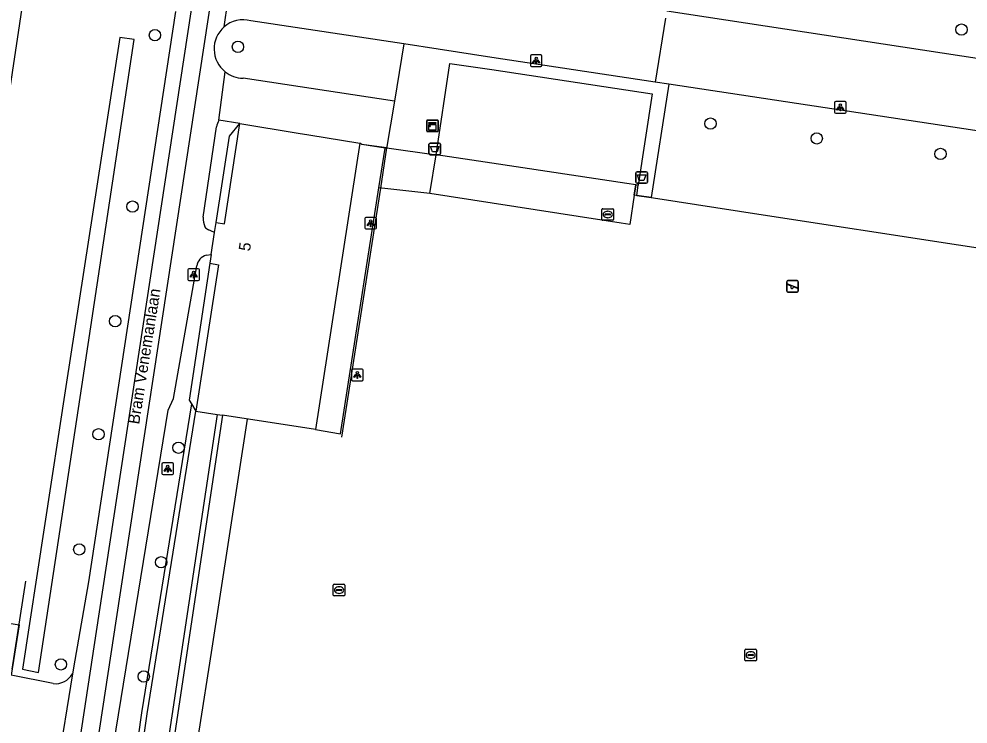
# Model space of a CAD drawing. Extents: x 161094 to 161705, y 379509 to 380907.
# Drawn here: x 161459.2 to 161541.1, y 380220.9 to 380281.7 of the extents above; entities that cross this region are included whole.
import ezdxf

# ---------------------------------------------------------------- set-up
doc = ezdxf.new("R2010")
doc.units = 0
for name, color, linetype in [('IMGEO_Afvalbak', 7, 'Continuous'), ('IMGEO_Boom', 7, 'Continuous'), ('IMGEO_Greppel_droge_sloot', 7, 'Continuous'), ('IMGEO_Groenvoorziening', 7, 'Continuous'), ('IMGEO_Hek', 7, 'Continuous'), ('IMGEO_Kast', 7, 'Continuous'), ('IMGEO_Lichtpunt', 7, 'Continuous'), ('IMGEO_Openbare_ruimte_label', 7, 'Continuous'), ('IMGEO_Pand', 7, 'Continuous'), ('IMGEO_Pand_nummerreeks', 7, 'Continuous'), ('IMGEO_Rijbaan_lokaal_gesloten', 7, 'Continuous'), ('IMGEO_Rijbaan_lokaal_open', 7, 'Continuous'), ('IMGEO_Speelvoorziening', 7, 'Continuous'), ('IMGEO_Voetpad_gesloten', 7, 'Continuous'), ('IMGEO_Voetpad_halfverhard', 7, 'Continuous'), ('IMGEO_Voetpad_open', 7, 'Continuous'), ('IMGEO_Waterleidingput', 7, 'Continuous'), ('IMGEO_Waterloop', 7, 'Continuous')]:
    doc.layers.add(name, color=color, linetype=linetype)

msp = doc.modelspace()

# ---------------------------------------------------------------- linework, layer by layer
at = {"layer": 'IMGEO_Afvalbak'}
for p, q in [((161494.577, 380270.094), (161494.577, 380270.894)), ((161494.577, 380270.894), (161494.577, 380270.094)), ((161494.677, 380270.994), (161495.467, 380270.994)), ((161495.467, 380270.994), (161494.677, 380270.994)), ((161495.567, 380270.894), (161495.567, 380270.094)), ((161495.567, 380270.094), (161495.567, 380270.894)), ((161495.467, 380269.994), (161494.677, 380269.994)), ((161494.677, 380269.994), (161495.467, 380269.994)), ((161512.428, 380267.629), (161512.428, 380268.429)), ((161512.428, 380268.429), (161512.428, 380267.629)), ((161512.528, 380268.529), (161513.318, 380268.529)), ((161513.318, 380268.529), (161512.528, 380268.529)), ((161513.418, 380268.429), (161513.418, 380267.629)), ((161513.418, 380267.629), (161513.418, 380268.429)), ((161513.318, 380267.529), (161512.528, 380267.529)), ((161512.528, 380267.529), (161513.318, 380267.529))]:
    msp.add_line(p, q, dxfattribs=at)
for points in [[(161494.72, 380270.708), (161495.424, 380270.708), (161495.275, 380270.238), (161494.869, 380270.238), (161494.72, 380270.708)], [(161512.571, 380268.243), (161513.275, 380268.243), (161513.126, 380267.773), (161512.72, 380267.773), (161512.571, 380268.243)]]:
    msp.add_lwpolyline(points, dxfattribs=at)
for centre, start, end in [((161494.677, 380270.894), 90, 180), ((161494.677, 380270.894), 90, 180), ((161495.467, 380270.894), 0, 90), ((161495.467, 380270.894), 360, 90), ((161494.677, 380270.094), 180, 270), ((161494.677, 380270.094), 180, 270), ((161495.467, 380270.094), 270, 0), ((161495.467, 380270.094), 270, 0), ((161512.528, 380268.429), 90, 180), ((161512.528, 380268.429), 90, 180), ((161513.318, 380268.429), 0, 90), ((161513.318, 380268.429), 360, 90), ((161512.528, 380267.629), 180, 270), ((161512.528, 380267.629), 180, 270), ((161513.318, 380267.629), 270, 0), ((161513.318, 380267.629), 270, 0)]:
    msp.add_arc(centre, 0.1, start, end, dxfattribs=at)
at = {"layer": 'IMGEO_Boom'}
for centre in [(161540.519, 380280.781), (161470.934, 380280.302), (161478.097, 380279.294), (161518.864, 380272.671), (161528.028, 380271.401), (161538.709, 380270.057), (161468.994, 380265.516), (161467.497, 380255.64), (161466.065, 380245.889), (161472.961, 380244.732), (161464.403, 380235.963), (161471.464, 380234.855), (161462.817, 380226.049), (161469.968, 380225.004)]:
    msp.add_circle(centre, 0.489, dxfattribs=at)
at = {"layer": 'IMGEO_Greppel_droge_sloot'}
msp.add_lwpolyline([(161469.146, 380279.911), (161467.896, 380280.089), (161463.253, 380250), (161459.495, 380225.647), (161460.876, 380225.356), (161464.612, 380250), (161469.146, 380279.911)], dxfattribs=at)
at = {"layer": 'IMGEO_Groenvoorziening'}
for points in [[(161476.2, 380264.154), (161477.368, 380271.592), (161478.255, 380272.694)], [(161512.415, 380267.391), (161512.279, 380266.508), (161511.902, 380263.976), (161511.145, 380264.094), (161494.657, 380266.645)], [(161475.658, 380260.635), (161473.892, 380248.836), (161474.092, 380248.508)], [(161474.092, 380248.508), (161469.784, 380221.87), (161463.517, 380177.6), (161462.422, 380170.033), (161462.392, 380169.879), (161462.385, 380169.673), (161462.409, 380169.469), (161462.437, 380169.367)], [(161474.092, 380248.508), (161474.472, 380247.886)], [(161476.761, 380247.535), (161466.509, 380179.329), (161465.043, 380169.711), (161465.035, 380169.551), (161465.006, 380169.36)]]:
    msp.add_lwpolyline(points, dxfattribs=at)
at = {"layer": 'IMGEO_Hek'}
for points in [[(161487.042, 380245.645), (161490.407, 380267.114), (161490.951, 380270.588)], [(161490.951, 380270.588), (161488.77, 380270.861)], [(161490.951, 380270.588), (161495.182, 380269.995)], [(161512.279, 380266.508), (161512.415, 380267.391)], [(161574.717, 380256.895), (161523.039, 380264.851), (161512.279, 380266.508)], [(161512.509, 380266.485), (161513.755, 380266.304)], [(161558.655, 380153.718), (161472.202, 380166.92), (161467.427, 380173.551), (161469.43, 380186.379), (161475.815, 380227.062), (161478.929, 380247.203)], [(161458.621, 380225.641), (161459.791, 380233.223)]]:
    msp.add_lwpolyline(points, dxfattribs=at)
at = {"layer": 'IMGEO_Kast'}
for p, q in [((161494.376, 380272.058), (161494.376, 380272.899)), ((161494.376, 380272.899), (161494.376, 380272.058)), ((161494.451, 380272.983), (161495.292, 380272.983)), ((161495.292, 380272.983), (161494.451, 380272.983)), ((161495.376, 380272.908), (161495.376, 380272.067)), ((161495.376, 380272.067), (161495.376, 380272.908)), ((161495.301, 380271.983), (161494.46, 380271.983)), ((161494.46, 380271.983), (161495.301, 380271.983))]:
    msp.add_line(p, q, dxfattribs=at)
for points in [[(161494.571, 380272.773), (161495.171, 380272.773), (161495.171, 380272.688), (161494.571, 380272.688), (161494.571, 380272.773)], [(161494.571, 380272.598), (161495.171, 380272.598), (161495.171, 380272.109), (161494.571, 380272.109), (161494.571, 380272.598)]]:
    msp.add_lwpolyline(points, dxfattribs=at)
msp.add_circle((161494.655, 380272.447), 0.0377, dxfattribs=at)
for centre, start, end in [((161494.454, 380272.905), 92.4484, 184.28452), ((161494.454, 380272.905), 92.4484, 184.28452), ((161495.298, 380272.905), 2.4484, 94.28452), ((161495.298, 380272.905), 2.4484, 94.28452), ((161494.454, 380272.061), 182.4484, 274.28452), ((161494.454, 380272.061), 182.4484, 274.28452), ((161495.298, 380272.061), 272.4484, 4.28452), ((161495.298, 380272.061), 272.4484, 4.28452)]:
    msp.add_arc(centre, 0.0779, start, end, dxfattribs=at)
at = {"layer": 'IMGEO_Lichtpunt'}
for p, q in [((161503.326, 380278.5), (161503.326, 380277.693)), ((161503.326, 380278.5), (161503.326, 380277.693)), ((161504.228, 380278.595), (161503.42, 380278.595)), ((161504.228, 380278.595), (161503.42, 380278.595)), ((161504.322, 380277.693), (161504.322, 380278.5)), ((161504.322, 380277.693), (161504.322, 380278.5)), ((161503.42, 380277.599), (161504.228, 380277.599)), ((161503.42, 380277.599), (161504.228, 380277.599)), ((161529.572, 380274.471), (161529.572, 380273.664)), ((161529.572, 380274.471), (161529.572, 380273.664)), ((161530.474, 380274.566), (161529.666, 380274.566)), ((161530.474, 380274.566), (161529.666, 380274.566)), ((161530.568, 380273.664), (161530.568, 380274.471)), ((161530.568, 380273.664), (161530.568, 380274.471)), ((161529.666, 380273.57), (161530.474, 380273.57)), ((161529.666, 380273.57), (161530.474, 380273.57)), ((161489.945, 380264.585), (161489.137, 380264.585)), ((161489.945, 380264.585), (161489.137, 380264.585)), ((161489.043, 380264.49), (161489.043, 380263.683)), ((161489.043, 380264.49), (161489.043, 380263.683)), ((161490.039, 380263.683), (161490.039, 380264.49)), ((161490.039, 380263.683), (161490.039, 380264.49)), ((161489.137, 380263.589), (161489.945, 380263.589)), ((161489.137, 380263.589), (161489.945, 380263.589)), ((161473.771, 380260.054), (161473.771, 380259.247)), ((161473.771, 380260.054), (161473.771, 380259.247)), ((161474.673, 380260.149), (161473.865, 380260.149)), ((161474.673, 380260.149), (161473.865, 380260.149)), ((161474.767, 380259.247), (161474.767, 380260.054)), ((161474.767, 380259.247), (161474.767, 380260.054)), ((161473.865, 380259.153), (161474.673, 380259.153)), ((161473.865, 380259.153), (161474.673, 380259.153)), ((161488.798, 380251.499), (161487.99, 380251.499)), ((161488.798, 380251.499), (161487.99, 380251.499)), ((161487.896, 380251.404), (161487.896, 380250.597)), ((161487.896, 380251.404), (161487.896, 380250.597)), ((161488.892, 380250.597), (161488.892, 380251.404)), ((161488.892, 380250.597), (161488.892, 380251.404)), ((161487.99, 380250.503), (161488.798, 380250.503)), ((161487.99, 380250.503), (161488.798, 380250.503)), ((161471.539, 380243.318), (161471.539, 380242.511)), ((161471.539, 380243.318), (161471.539, 380242.511)), ((161472.441, 380243.413), (161471.633, 380243.413)), ((161472.441, 380243.413), (161471.633, 380243.413)), ((161472.535, 380242.511), (161472.535, 380243.318)), ((161472.535, 380242.511), (161472.535, 380243.318)), ((161471.633, 380242.417), (161472.441, 380242.417)), ((161471.633, 380242.417), (161472.441, 380242.417))]:
    msp.add_line(p, q, dxfattribs=at)
for points in [[(161503.7, 380278.164), (161503.739, 380278.136), (161503.551, 380277.874), (161503.513, 380277.901), (161503.7, 380278.164)], [(161503.802, 380278.116), (161503.849, 380278.116), (161503.849, 380277.794), (161503.802, 380277.794), (161503.802, 380278.116)], [(161503.912, 380278.136), (161503.95, 380278.163), (161504.137, 380277.901), (161504.098, 380277.873), (161503.912, 380278.136)], [(161529.946, 380274.135), (161529.985, 380274.107), (161529.797, 380273.845), (161529.759, 380273.872), (161529.946, 380274.135)], [(161530.048, 380274.087), (161530.095, 380274.087), (161530.095, 380273.765), (161530.048, 380273.765), (161530.048, 380274.087)], [(161530.158, 380274.107), (161530.196, 380274.134), (161530.383, 380273.872), (161530.344, 380273.844), (161530.158, 380274.107)], [(161489.417, 380264.154), (161489.456, 380264.126), (161489.268, 380263.864), (161489.23, 380263.891), (161489.417, 380264.154)], [(161489.519, 380264.106), (161489.566, 380264.106), (161489.566, 380263.784), (161489.519, 380263.784), (161489.519, 380264.106)], [(161489.629, 380264.126), (161489.667, 380264.153), (161489.854, 380263.891), (161489.815, 380263.863), (161489.629, 380264.126)], [(161474.145, 380259.718), (161474.184, 380259.69), (161473.996, 380259.428), (161473.958, 380259.455), (161474.145, 380259.718)], [(161474.247, 380259.67), (161474.294, 380259.67), (161474.294, 380259.348), (161474.247, 380259.348), (161474.247, 380259.67)], [(161474.357, 380259.69), (161474.395, 380259.717), (161474.582, 380259.455), (161474.543, 380259.427), (161474.357, 380259.69)], [(161488.27, 380251.068), (161488.309, 380251.04), (161488.121, 380250.778), (161488.083, 380250.805), (161488.27, 380251.068)], [(161488.372, 380251.02), (161488.419, 380251.02), (161488.419, 380250.698), (161488.372, 380250.698), (161488.372, 380251.02)], [(161488.482, 380251.04), (161488.52, 380251.067), (161488.707, 380250.805), (161488.668, 380250.777), (161488.482, 380251.04)], [(161471.913, 380242.982), (161471.952, 380242.954), (161471.764, 380242.692), (161471.726, 380242.719), (161471.913, 380242.982)], [(161472.015, 380242.934), (161472.062, 380242.934), (161472.062, 380242.612), (161472.015, 380242.612), (161472.015, 380242.934)], [(161472.125, 380242.954), (161472.163, 380242.981), (161472.35, 380242.719), (161472.311, 380242.691), (161472.125, 380242.954)]]:
    msp.add_lwpolyline(points, dxfattribs=at)
for centre in [(161503.825, 380278.298), (161530.071, 380274.269), (161489.542, 380264.288), (161474.27, 380259.852), (161488.395, 380251.202), (161472.038, 380243.116)]:
    msp.add_circle(centre, 0.0994, dxfattribs=at)
for centre, start, end in [((161503.42, 380278.5), 90, 180), ((161503.42, 380278.5), 90, 180), ((161504.228, 380278.5), 0, 90), ((161504.228, 380278.5), 0, 90), ((161503.42, 380277.693), 180, 270), ((161503.42, 380277.693), 180, 270), ((161504.228, 380277.693), 270, 0), ((161504.228, 380277.693), 270, 360), ((161529.666, 380274.471), 90, 180), ((161529.666, 380274.471), 90, 180), ((161530.474, 380274.471), 0, 90), ((161530.474, 380274.471), 0, 90), ((161529.666, 380273.664), 180, 270), ((161529.666, 380273.664), 180, 270), ((161530.474, 380273.664), 270, 0), ((161530.474, 380273.664), 270, 360), ((161489.137, 380264.49), 90, 180), ((161489.137, 380264.49), 90, 180), ((161489.945, 380264.49), 0, 90), ((161489.945, 380264.49), 0, 90), ((161489.137, 380263.683), 180, 270), ((161489.137, 380263.683), 180, 270), ((161489.945, 380263.683), 270, 0), ((161489.945, 380263.683), 270, 360), ((161473.865, 380260.054), 90, 180), ((161473.865, 380260.054), 90, 180), ((161474.673, 380260.054), 0, 90), ((161474.673, 380260.054), 0, 90), ((161473.865, 380259.247), 180, 270), ((161473.865, 380259.247), 180, 270), ((161474.673, 380259.247), 270, 0), ((161474.673, 380259.247), 270, 360), ((161487.99, 380251.404), 90, 180), ((161487.99, 380251.404), 90, 180), ((161488.798, 380251.404), 0, 90), ((161488.798, 380251.404), 0, 90), ((161487.99, 380250.597), 180, 270), ((161487.99, 380250.597), 180, 270), ((161488.798, 380250.597), 270, 0), ((161488.798, 380250.597), 270, 360), ((161471.633, 380243.318), 90, 180), ((161471.633, 380243.318), 90, 180), ((161472.441, 380243.318), 0, 90), ((161472.441, 380243.318), 0, 90), ((161471.633, 380242.511), 180, 270), ((161471.633, 380242.511), 180, 270), ((161472.441, 380242.511), 270, 0), ((161472.441, 380242.511), 270, 360)]:
    msp.add_arc(centre, 0.0946, start, end, dxfattribs=at)
at = {"layer": 'IMGEO_Pand'}
for points in [[(161445.404, 380233.707), (161445.627, 380235.147), (161446.05, 380235.084), (161452.191, 380234.169), (161452.226, 380234.4), (161454.566, 380250), (161468.027, 380339.705), (161467.674, 380339.759)], [(161495.182, 380269.995), (161496.387, 380277.87), (161500, 380277.328), (161513.842, 380275.25), (161512.618, 380267.36)], [(161476.2, 380264.154), (161476.94, 380264.03), (161478.255, 380272.694)], [(161478.255, 380272.694), (161483.281, 380271.863), (161484.207, 380271.71), (161488.622, 380270.98)], [(161488.622, 380270.98), (161484.775, 380246.307)], [(161512.415, 380267.391), (161511.66, 380267.505), (161500, 380269.267), (161495.182, 380269.995)], [(161512.618, 380267.36), (161512.415, 380267.391)], [(161476.066, 380263.282), (161476.2, 380264.154)], [(161475.772, 380261.375), (161476.066, 380263.282)], [(161475.772, 380261.375), (161475.658, 380260.635)], [(161475.658, 380260.635), (161476.425, 380260.498), (161474.472, 380247.886)], [(161474.472, 380247.886), (161476.294, 380247.607)], [(161476.294, 380247.607), (161476.761, 380247.535)], [(161484.775, 380246.307), (161476.761, 380247.535)]]:
    msp.add_lwpolyline(points, dxfattribs=at)
at = {"layer": 'IMGEO_Rijbaan_lokaal_gesloten'}
for points in [[(161500.797, 380441.248), (161498.535, 380426.719), (161497.303, 380424.898), (161496.967, 380422.687), (161487.325, 380359.344), (161487.307, 380359.083), (161485.505, 380347.041), (161467.599, 380229.99), (161457.567, 380164.364), (161456.074, 380164.596), (161466.094, 380230.202), (161483.979, 380347.225), (161485.809, 380359.378), (161485.861, 380359.57), (161495.524, 380423.042), (161498.373, 380441.757)], [(161476.894, 380281.005), (161478.163, 380289.777)], [(161472.691, 380282.325), (161465.207, 380233.179), (161464.029, 380226.403), (161463.827, 380225.238)], [(161492.398, 380279.538), (161479.202, 380281.544)], [(161514.984, 380281.757), (161514.092, 380276.241)], [(161514.092, 380276.241), (161500, 380278.383), (161495.36, 380279.088), (161492.398, 380279.538)], [(161476.447, 380272.956), (161476.982, 380277.141)], [(161475.082, 380264.596), (161476.248, 380272.398)], [(161476.066, 380263.282), (161476.007, 380263.315), (161475.555, 380263.529)], [(161475.343, 380261.323), (161475.772, 380261.375)], [(161459.926, 380169.997), (161464.514, 380200.592), (161467.572, 380220.455), (161472.065, 380247.978), (161472.522, 380248.965), (161474.536, 380260.41)], [(161463.827, 380225.238), (161462.538, 380217.249), (161462.38, 380216.189)]]:
    msp.add_lwpolyline(points, dxfattribs=at)
for centre, radius, start, end in [((161478.554, 380279.11), 2.519, 131.2084, 231.40089), ((161478.553, 380279.11), 2.519, 75.08028, 131.20974), ((161478.34, 380271.966), 2.136, 152.40098, 168.34342), ((161477.584, 380264.669), 2.503, 181.6754, 201.05116), ((161475.707, 380264.038), 0.531, 210.32108, 253.41394), ((161475.716, 380260.18), 1.202, 108.0641, 168.98902)]:
    msp.add_arc(centre, radius, start, end, dxfattribs=at)
at = {"layer": 'IMGEO_Rijbaan_lokaal_open'}
for points in [[(161574.117, 380277.813), (161571.082, 380273.823), (161515.085, 380282.382)], [(161574.117, 380277.813), (161578.015, 380277.213), (161578.015, 380271.799), (161576.918, 380266.95), (161571.501, 380267.574), (161515.278, 380276.061)], [(161515.278, 380276.061), (161514.092, 380276.241)]]:
    msp.add_lwpolyline(points, dxfattribs=at)
at = {"layer": 'IMGEO_Speelvoorziening'}
for p, q in [((161525.449, 380258.238), (161525.449, 380259.038)), ((161525.449, 380259.038), (161525.449, 380258.238)), ((161525.518, 380258.863), (161526.394, 380258.51)), ((161525.549, 380259.138), (161526.339, 380259.138)), ((161526.339, 380259.138), (161525.549, 380259.138)), ((161526.439, 380259.038), (161526.439, 380258.238)), ((161526.439, 380258.238), (161526.439, 380259.038)), ((161525.832, 380258.666), (161525.493, 380258.803)), ((161526.339, 380258.138), (161525.549, 380258.138)), ((161525.549, 380258.138), (161526.339, 380258.138)), ((161526.37, 380258.45), (161526.03, 380258.587))]:
    msp.add_line(p, q, dxfattribs=at)
for centre, radius, start, end in [((161525.549, 380259.038), 0.1, 90, 180), ((161525.549, 380259.038), 0.1, 90, 180), ((161525.506, 380258.833), 0.0327, 68.07798, 248.07798), ((161526.339, 380259.038), 0.1, 0, 90), ((161526.339, 380259.038), 0.1, 360, 90), ((161525.549, 380258.238), 0.1, 180, 270), ((161525.549, 380258.238), 0.1, 180, 270), ((161525.911, 380258.576), 0.12, 130.99278, 5.16318), ((161526.339, 380258.238), 0.1, 270, 0), ((161526.339, 380258.238), 0.1, 270, 0), ((161526.382, 380258.48), 0.0327, 248.07798, 68.07798)]:
    msp.add_arc(centre, radius, start, end, dxfattribs=at)
at = {"layer": 'IMGEO_Voetpad_gesloten'}
msp.add_lwpolyline([(161445.404, 380233.707), (161445.183, 380231.716), (161459.211, 380229.466), (161458.539, 380225.11)], dxfattribs=at)
at = {"layer": 'IMGEO_Voetpad_halfverhard'}
for points in [[(161491.599, 380274.601), (161478.535, 380276.59)], [(161478.255, 380272.694), (161476.447, 380272.956)]]:
    msp.add_lwpolyline(points, dxfattribs=at)
msp.add_arc((161478.555, 380279.109), 2.519, 231.3763, 269.55462, dxfattribs=at)
at = {"layer": 'IMGEO_Voetpad_open'}
for points in [[(161492.398, 380279.538), (161491.599, 380274.601)], [(161515.278, 380276.061), (161513.755, 380266.304), (161512.509, 380266.485), (161512.618, 380267.36)], [(161491.599, 380274.601), (161490.897, 380270.531), (161490.783, 380270.549)], [(161490.783, 380270.549), (161488.77, 380270.861), (161488.622, 380270.98)], [(161490.25, 380267.131), (161490.783, 380270.549)], [(161494.657, 380266.645), (161495.182, 380269.995)], [(161484.775, 380246.307), (161486.942, 380245.925), (161487.578, 380250), (161490.25, 380267.131)], [(161494.657, 380266.645), (161490.25, 380267.131)], [(161462.153, 380224.392), (161458.539, 380225.11)]]:
    msp.add_lwpolyline(points, dxfattribs=at)
msp.add_arc((161462.329, 380226.123), 1.74, 264.19738, 329.42453, dxfattribs=at)
at = {"layer": 'IMGEO_Waterleidingput'}
for p, q in [((161509.5, 380264.412), (161509.5, 380265.264)), ((161509.575, 380265.338), (161510.427, 380265.338)), ((161509.759, 380264.832), (161509.759, 380264.844)), ((161510.197, 380264.795), (161509.799, 380264.795)), ((161509.802, 380264.881), (161510.2, 380264.881)), ((161509.988, 380265.118), (161510.013, 380265.118)), ((161510.243, 380264.844), (161510.243, 380264.832)), ((161510.501, 380265.264), (161510.501, 380264.412)), ((161510.427, 380264.338), (161509.575, 380264.338)), ((161510.011, 380264.558), (161509.986, 380264.558)), ((161486.316, 380232.026), (161486.316, 380232.878)), ((161486.391, 380232.952), (161487.243, 380232.952)), ((161486.804, 380232.732), (161486.829, 380232.732)), ((161487.317, 380232.878), (161487.317, 380232.026)), ((161487.243, 380231.952), (161486.391, 380231.952)), ((161486.575, 380232.446), (161486.575, 380232.458)), ((161487.013, 380232.409), (161486.615, 380232.409)), ((161486.618, 380232.495), (161487.016, 380232.495)), ((161486.827, 380232.172), (161486.802, 380232.172)), ((161487.059, 380232.458), (161487.059, 380232.446)), ((161521.831, 380226.424), (161521.831, 380227.276)), ((161521.906, 380227.35), (161522.758, 380227.35)), ((161522.319, 380227.13), (161522.344, 380227.13)), ((161522.832, 380227.276), (161522.832, 380226.424)), ((161522.758, 380226.35), (161521.906, 380226.35)), ((161522.09, 380226.844), (161522.09, 380226.856)), ((161522.528, 380226.807), (161522.13, 380226.807)), ((161522.133, 380226.893), (161522.531, 380226.893)), ((161522.342, 380226.57), (161522.317, 380226.57)), ((161522.574, 380226.856), (161522.574, 380226.844))]:
    msp.add_line(p, q, dxfattribs=at)
for points in [[(161509.5, 380264.412), (161509.5, 380265.264)], [(161509.575, 380265.338), (161510.427, 380265.338)], [(161510.501, 380265.264), (161510.501, 380264.412)], [(161510.427, 380264.338), (161509.575, 380264.338)], [(161486.316, 380232.026), (161486.316, 380232.878)], [(161486.391, 380232.952), (161487.243, 380232.952)], [(161487.317, 380232.878), (161487.317, 380232.026)], [(161487.243, 380231.952), (161486.391, 380231.952)], [(161521.831, 380226.424), (161521.831, 380227.276)], [(161521.906, 380227.35), (161522.758, 380227.35)], [(161522.832, 380227.276), (161522.832, 380226.424)], [(161522.758, 380226.35), (161521.906, 380226.35)]]:
    msp.add_lwpolyline(points, dxfattribs=at)
for centre, radius, start, end in [((161509.577, 380265.262), 0.0765, 91.55205, 178.44795), ((161509.577, 380265.262), 0.0765, 91.55205, 178.44795), ((161509.799, 380264.841), 0.0403, 85.87752, 175.75265), ((161509.796, 380264.831), 0.0366, 178.93798, 274.71019), ((161510.2, 380264.838), 0.043, 264.86636, 352.45326), ((161510.204, 380264.843), 0.0386, 1.73085, 96.63898), ((161510.425, 380265.262), 0.0765, 1.55205, 88.44795), ((161510.425, 380265.262), 0.0765, 1.55205, 88.44795), ((161509.577, 380264.414), 0.0765, 181.55205, 268.44795), ((161509.577, 380264.414), 0.0765, 181.55205, 268.44795), ((161510.425, 380264.414), 0.0765, 271.55205, 358.44795), ((161510.425, 380264.414), 0.0765, 271.55205, 358.44795), ((161486.393, 380232.876), 0.0765, 91.55205, 178.44795), ((161486.393, 380232.876), 0.0765, 91.55205, 178.44795), ((161487.241, 380232.876), 0.0765, 1.55205, 88.44795), ((161487.241, 380232.876), 0.0765, 1.55205, 88.44795), ((161486.393, 380232.028), 0.0765, 181.55205, 268.44795), ((161486.393, 380232.028), 0.0765, 181.55205, 268.44795), ((161486.615, 380232.455), 0.0403, 85.87752, 175.75265), ((161486.612, 380232.445), 0.0366, 178.93798, 274.71019), ((161487.016, 380232.452), 0.043, 264.86636, 352.45326), ((161487.02, 380232.457), 0.0386, 1.73085, 96.63898), ((161487.241, 380232.028), 0.0765, 271.55205, 358.44795), ((161487.241, 380232.028), 0.0765, 271.55205, 358.44795), ((161521.908, 380227.274), 0.0765, 91.55205, 178.44795), ((161521.908, 380227.274), 0.0765, 91.55205, 178.44795), ((161522.756, 380227.274), 0.0765, 1.55205, 88.44795), ((161522.756, 380227.274), 0.0765, 1.55205, 88.44795), ((161521.908, 380226.426), 0.0765, 181.55205, 268.44795), ((161521.908, 380226.426), 0.0765, 181.55205, 268.44795), ((161522.13, 380226.853), 0.0403, 85.87752, 175.75265), ((161522.127, 380226.843), 0.0366, 178.93798, 274.71019), ((161522.531, 380226.85), 0.043, 264.86636, 352.45326), ((161522.535, 380226.855), 0.0386, 1.73085, 96.63898), ((161522.756, 380226.426), 0.0765, 271.55205, 358.44795), ((161522.756, 380226.426), 0.0765, 271.55205, 358.44795)]:
    msp.add_arc(centre, radius, start, end, dxfattribs=at)
for centre, major_axis, ratio, start_param, end_param in [((161509.987, 380264.838), (-0.387, 0.002), 0.722429, 4.712389, 7.853982), ((161510.012, 380264.838), (-0.39, 0.002), 0.717154, 1.570796, 4.712389), ((161486.803, 380232.452), (-0.387, 0.002), 0.722429, 4.712389, 7.853982), ((161486.828, 380232.452), (-0.39, 0.002), 0.717154, 1.570796, 4.712389), ((161522.318, 380226.85), (-0.387, 0.002), 0.722429, 4.712389, 7.853982), ((161522.343, 380226.85), (-0.39, 0.002), 0.717154, 1.570796, 4.712389)]:
    msp.add_ellipse(centre, major_axis=major_axis, ratio=ratio, start_param=start_param, end_param=end_param, dxfattribs=at)
at = {"layer": 'IMGEO_Waterloop'}
for points in [[(161462.892, 380169.953), (161463.988, 380177.533), (161470.255, 380221.799), (161474.472, 380247.886)], [(161476.294, 380247.607), (161466.038, 380179.4), (161464.568, 380169.758)]]:
    msp.add_lwpolyline(points, dxfattribs=at)

# ---------------------------------------------------------------- texts
at = {"layer": 'IMGEO_Openbare_ruimte_label'}
msp.add_text('Bram Venemanlaan', height=1, rotation=80.9708, dxfattribs=at).set_placement((161469.564, 380246.701))
at = {"layer": 'IMGEO_Pand_nummerreeks'}
msp.add_text('5', height=1, rotation=81.24542, dxfattribs=at).set_placement((161479.129, 380261.626))

doc.saveas('drawing.dxf')
